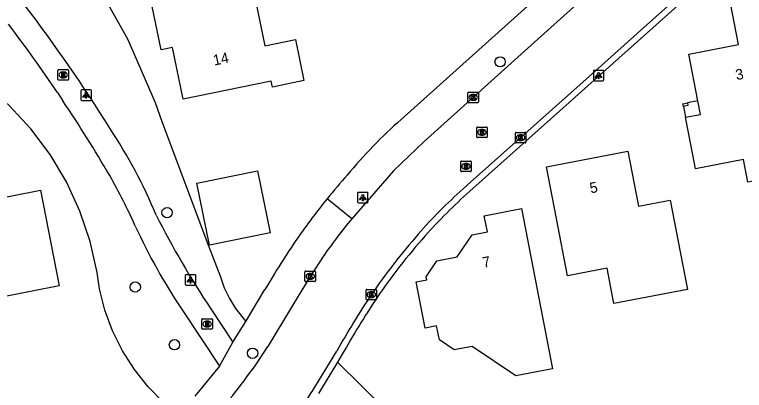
# Model space of a CAD drawing. Extents: x 157663 to 158496, y 379212 to 380934.
# Drawn here: x 158279.6 to 158348.7, y 380434.7 to 380470.3 of the extents above; entities that cross this region are included whole.
import ezdxf

# ---------------------------------------------------------------- set-up
doc = ezdxf.new("R2010")
doc.units = 0
for name, color, linetype in [('IMGEO_Boom', 7, 'Continuous'), ('IMGEO_Groenvoorziening', 7, 'Continuous'), ('IMGEO_Kolk', 7, 'Continuous'), ('IMGEO_Lichtpunt', 7, 'Continuous'), ('IMGEO_Pand', 7, 'Continuous'), ('IMGEO_Pand_nummerreeks', 7, 'Continuous'), ('IMGEO_Pand_overbouw', 7, 'Continuous'), ('IMGEO_Rijbaan_lokaal_open', 7, 'Continuous'), ('IMGEO_Rioolput', 7, 'Continuous'), ('IMGEO_Voetpad_open', 7, 'Continuous')]:
    doc.layers.add(name, color=color, linetype=linetype)

msp = doc.modelspace()

# ---------------------------------------------------------------- linework, layer by layer
at = {"layer": 'IMGEO_Boom'}
for centre in [(158325.596, 380465.83), (158294.038, 380451.528), (158291.024, 380444.477), (158294.741, 380439.004), (158302.147, 380438.192)]:
    msp.add_circle(centre, 0.489, dxfattribs=at)
at = {"layer": 'IMGEO_Groenvoorziening'}
for points in [[(158346.995, 380524.313), (158343.154, 380528.231), (158314.078, 380500), (158287.061, 380473.748), (158290.289, 380468.019), (158292.901, 380461.983), (158293.548, 380460.157), (158297.957, 380448.38), (158299.09, 380445.455), (158299.464, 380444.4), (158299.946, 380443.389), (158300.531, 380442.435), (158301.507, 380441.214)], [(158295.076, 380432.348), (158293.72, 380433.506), (158292.249, 380435.007), (158290.942, 380436.654), (158289.815, 380438.428), (158288.879, 380440.31), (158288.146, 380442.279), (158287.622, 380444.315), (158287.402, 380445.849), (158286.736, 380448.807), (158285.765, 380451.68), (158284.499, 380454.435), (158282.951, 380457.043), (158281.14, 380459.474), (158279.084, 380461.703), (158276.807, 380463.705), (158276.529, 380463.435)], [(158310.18, 380437.339), (158314.722, 380432.862), (158316.188, 380431.36), (158320.425, 380427.602), (158325.031, 380424.307), (158329.956, 380421.512), (158334.859, 380419.373)]]:
    msp.add_lwpolyline(points, dxfattribs=at)
at = {"layer": 'IMGEO_Kolk'}
for p, q in [((158322.545, 380462.026), (158322.545, 380462.878)), ((158322.62, 380462.952), (158323.472, 380462.952)), ((158323.546, 380462.878), (158323.546, 380462.026)), ((158323.056, 380462.172), (158323.031, 380462.172)), ((158323.033, 380462.732), (158323.058, 380462.732)), ((158323.472, 380461.952), (158322.62, 380461.952)), ((158327.043, 380458.213), (158327.043, 380459.065)), ((158327.118, 380459.139), (158327.97, 380459.139)), ((158327.531, 380458.919), (158327.556, 380458.919)), ((158328.044, 380459.065), (158328.044, 380458.213)), ((158327.97, 380458.139), (158327.118, 380458.139)), ((158327.554, 380458.359), (158327.529, 380458.359)), ((158307.105, 380445.063), (158307.105, 380445.915)), ((158307.18, 380445.989), (158308.032, 380445.989)), ((158307.593, 380445.769), (158307.618, 380445.769)), ((158308.106, 380445.915), (158308.106, 380445.063)), ((158308.032, 380444.989), (158307.18, 380444.989)), ((158307.616, 380445.209), (158307.591, 380445.209)), ((158312.89, 380443.33), (158312.89, 380444.182)), ((158312.965, 380444.256), (158313.817, 380444.256)), ((158313.891, 380444.182), (158313.891, 380443.33)), ((158313.401, 380443.476), (158313.376, 380443.476)), ((158313.378, 380444.036), (158313.403, 380444.036)), ((158313.817, 380443.256), (158312.965, 380443.256))]:
    msp.add_line(p, q, dxfattribs=at)
for points in [[(158322.545, 380462.026), (158322.545, 380462.878)], [(158322.62, 380462.952), (158323.472, 380462.952)], [(158323.546, 380462.878), (158323.546, 380462.026)], [(158322.866, 380462.652), (158322.989, 380462.652), (158322.989, 380462.501), (158323.119, 380462.652), (158323.283, 380462.652), (158323.137, 380462.501), (158323.29, 380462.252), (158323.138, 380462.252), (158323.053, 380462.416), (158322.989, 380462.349), (158322.989, 380462.252), (158322.866, 380462.252), (158322.866, 380462.652)], [(158323.472, 380461.952), (158322.62, 380461.952)], [(158327.043, 380458.213), (158327.043, 380459.065)], [(158327.118, 380459.139), (158327.97, 380459.139)], [(158327.364, 380458.839), (158327.487, 380458.839), (158327.487, 380458.688), (158327.617, 380458.839), (158327.781, 380458.839), (158327.635, 380458.688), (158327.788, 380458.439), (158327.636, 380458.439), (158327.551, 380458.603), (158327.487, 380458.536), (158327.487, 380458.439), (158327.364, 380458.439), (158327.364, 380458.839)], [(158328.044, 380459.065), (158328.044, 380458.213)], [(158327.97, 380458.139), (158327.118, 380458.139)], [(158307.105, 380445.063), (158307.105, 380445.915)], [(158307.18, 380445.989), (158308.032, 380445.989)], [(158307.426, 380445.689), (158307.549, 380445.689), (158307.549, 380445.538), (158307.679, 380445.689), (158307.843, 380445.689), (158307.697, 380445.538), (158307.85, 380445.289), (158307.698, 380445.289), (158307.613, 380445.453), (158307.549, 380445.386), (158307.549, 380445.289), (158307.426, 380445.289), (158307.426, 380445.689)], [(158308.106, 380445.915), (158308.106, 380445.063)], [(158308.032, 380444.989), (158307.18, 380444.989)], [(158312.89, 380443.33), (158312.89, 380444.182)], [(158312.965, 380444.256), (158313.817, 380444.256)], [(158313.891, 380444.182), (158313.891, 380443.33)], [(158313.211, 380443.956), (158313.334, 380443.956), (158313.334, 380443.805), (158313.464, 380443.956), (158313.628, 380443.956), (158313.482, 380443.805), (158313.635, 380443.556), (158313.483, 380443.556), (158313.398, 380443.72), (158313.334, 380443.653), (158313.334, 380443.556), (158313.211, 380443.556), (158313.211, 380443.956)], [(158313.817, 380443.256), (158312.965, 380443.256)]]:
    msp.add_lwpolyline(points, dxfattribs=at)
for centre, start, end in [((158322.622, 380462.876), 91.55205, 178.44795), ((158322.622, 380462.876), 91.55205, 178.44795), ((158323.47, 380462.876), 1.55205, 88.44795), ((158323.47, 380462.876), 1.55205, 88.44795), ((158322.622, 380462.028), 181.55205, 268.44795), ((158322.622, 380462.028), 181.55205, 268.44795), ((158323.47, 380462.028), 271.55205, 358.44795), ((158323.47, 380462.028), 271.55205, 358.44795), ((158327.12, 380459.063), 91.55205, 178.44795), ((158327.12, 380459.063), 91.55205, 178.44795), ((158327.968, 380459.063), 1.55205, 88.44795), ((158327.968, 380459.063), 1.55205, 88.44795), ((158327.12, 380458.215), 181.55205, 268.44795), ((158327.12, 380458.215), 181.55205, 268.44795), ((158327.968, 380458.215), 271.55205, 358.44795), ((158327.968, 380458.215), 271.55205, 358.44795), ((158307.182, 380445.913), 91.55205, 178.44795), ((158307.182, 380445.913), 91.55205, 178.44795), ((158308.03, 380445.913), 1.55205, 88.44795), ((158308.03, 380445.913), 1.55205, 88.44795), ((158307.182, 380445.065), 181.55205, 268.44795), ((158307.182, 380445.065), 181.55205, 268.44795), ((158308.03, 380445.065), 271.55205, 358.44795), ((158308.03, 380445.065), 271.55205, 358.44795), ((158312.967, 380444.18), 91.55205, 178.44795), ((158312.967, 380444.18), 91.55205, 178.44795), ((158313.815, 380444.18), 1.55205, 88.44795), ((158313.815, 380444.18), 1.55205, 88.44795), ((158312.967, 380443.332), 181.55205, 268.44795), ((158312.967, 380443.332), 181.55205, 268.44795), ((158313.815, 380443.332), 271.55205, 358.44795), ((158313.815, 380443.332), 271.55205, 358.44795)]:
    msp.add_arc(centre, 0.0765, start, end, dxfattribs=at)
for centre, major_axis, ratio, start_param, end_param in [((158323.032, 380462.452), (-0.387, 0.002), 0.722429, 4.712389, 7.853982), ((158323.057, 380462.452), (-0.39, 0.002), 0.717154, 1.570796, 4.712389), ((158327.53, 380458.639), (-0.387, 0.002), 0.722429, 4.712389, 7.853982), ((158327.555, 380458.639), (-0.39, 0.002), 0.717154, 1.570796, 4.712389), ((158307.592, 380445.489), (-0.387, 0.002), 0.722429, 4.712389, 7.853982), ((158307.617, 380445.489), (-0.39, 0.002), 0.717154, 1.570796, 4.712389), ((158313.377, 380443.756), (-0.387, 0.002), 0.722429, 4.712389, 7.853982), ((158313.402, 380443.756), (-0.39, 0.002), 0.717154, 1.570796, 4.712389)]:
    msp.add_ellipse(centre, major_axis=major_axis, ratio=ratio, start_param=start_param, end_param=end_param, dxfattribs=at)
at = {"layer": 'IMGEO_Lichtpunt'}
for p, q in [((158334.43, 380464.926), (158334.43, 380464.119)), ((158334.43, 380464.926), (158334.43, 380464.119)), ((158335.332, 380465.021), (158334.524, 380465.021)), ((158335.332, 380465.021), (158334.524, 380465.021)), ((158335.426, 380464.119), (158335.426, 380464.926)), ((158335.426, 380464.119), (158335.426, 380464.926)), ((158334.524, 380464.025), (158335.332, 380464.025)), ((158334.524, 380464.025), (158335.332, 380464.025)), ((158285.88, 380463.079), (158285.88, 380462.272)), ((158285.88, 380463.079), (158285.88, 380462.272)), ((158286.782, 380463.174), (158285.974, 380463.174)), ((158286.782, 380463.174), (158285.974, 380463.174)), ((158286.876, 380462.272), (158286.876, 380463.079)), ((158286.876, 380462.272), (158286.876, 380463.079)), ((158285.974, 380462.178), (158286.782, 380462.178)), ((158285.974, 380462.178), (158286.782, 380462.178)), ((158312.081, 380453.358), (158312.081, 380452.551)), ((158312.081, 380453.358), (158312.081, 380452.551)), ((158312.983, 380453.453), (158312.175, 380453.453)), ((158312.983, 380453.453), (158312.175, 380453.453)), ((158313.077, 380452.551), (158313.077, 380453.358)), ((158313.077, 380452.551), (158313.077, 380453.358)), ((158312.175, 380452.457), (158312.983, 380452.457)), ((158312.175, 380452.457), (158312.983, 380452.457)), ((158295.754, 380445.552), (158295.754, 380444.745)), ((158295.754, 380445.552), (158295.754, 380444.745)), ((158296.656, 380445.647), (158295.848, 380445.647)), ((158296.656, 380445.647), (158295.848, 380445.647)), ((158296.75, 380444.745), (158296.75, 380445.552)), ((158296.75, 380444.745), (158296.75, 380445.552)), ((158295.848, 380444.651), (158296.656, 380444.651)), ((158295.848, 380444.651), (158296.656, 380444.651))]:
    msp.add_line(p, q, dxfattribs=at)
for points in [[(158334.804, 380464.59), (158334.843, 380464.562), (158334.655, 380464.3), (158334.617, 380464.327), (158334.804, 380464.59)], [(158334.906, 380464.542), (158334.953, 380464.542), (158334.953, 380464.22), (158334.906, 380464.22), (158334.906, 380464.542)], [(158335.016, 380464.562), (158335.054, 380464.589), (158335.241, 380464.327), (158335.202, 380464.299), (158335.016, 380464.562)], [(158286.254, 380462.743), (158286.293, 380462.715), (158286.105, 380462.453), (158286.067, 380462.48), (158286.254, 380462.743)], [(158286.356, 380462.695), (158286.403, 380462.695), (158286.403, 380462.373), (158286.356, 380462.373), (158286.356, 380462.695)], [(158286.466, 380462.715), (158286.504, 380462.742), (158286.691, 380462.48), (158286.652, 380462.452), (158286.466, 380462.715)], [(158312.455, 380453.022), (158312.494, 380452.994), (158312.306, 380452.732), (158312.268, 380452.759), (158312.455, 380453.022)], [(158312.557, 380452.974), (158312.604, 380452.974), (158312.604, 380452.652), (158312.557, 380452.652), (158312.557, 380452.974)], [(158312.667, 380452.994), (158312.705, 380453.021), (158312.892, 380452.759), (158312.853, 380452.731), (158312.667, 380452.994)], [(158296.128, 380445.216), (158296.167, 380445.188), (158295.979, 380444.926), (158295.941, 380444.953), (158296.128, 380445.216)], [(158296.23, 380445.168), (158296.277, 380445.168), (158296.277, 380444.846), (158296.23, 380444.846), (158296.23, 380445.168)], [(158296.34, 380445.188), (158296.378, 380445.215), (158296.565, 380444.953), (158296.526, 380444.925), (158296.34, 380445.188)]]:
    msp.add_lwpolyline(points, dxfattribs=at)
for centre in [(158334.929, 380464.724), (158286.379, 380462.877), (158312.58, 380453.156), (158296.253, 380445.35)]:
    msp.add_circle(centre, 0.0994, dxfattribs=at)
for centre, start, end in [((158334.524, 380464.926), 90, 180), ((158334.524, 380464.926), 90, 180), ((158335.332, 380464.926), 0, 90), ((158335.332, 380464.926), 0, 90), ((158334.524, 380464.119), 180, 270), ((158334.524, 380464.119), 180, 270), ((158335.332, 380464.119), 270, 0), ((158335.332, 380464.119), 270, 360), ((158285.974, 380463.079), 90, 180), ((158285.974, 380463.079), 90, 180), ((158286.782, 380463.079), 0, 90), ((158286.782, 380463.079), 0, 90), ((158285.974, 380462.272), 180, 270), ((158285.974, 380462.272), 180, 270), ((158286.782, 380462.272), 270, 0), ((158286.782, 380462.272), 270, 360), ((158312.175, 380453.358), 90, 180), ((158312.175, 380453.358), 90, 180), ((158312.983, 380453.358), 0, 90), ((158312.983, 380453.358), 0, 90), ((158312.175, 380452.551), 180, 270), ((158312.175, 380452.551), 180, 270), ((158312.983, 380452.551), 270, 0), ((158312.983, 380452.551), 270, 360), ((158295.848, 380445.552), 90, 180), ((158295.848, 380445.552), 90, 180), ((158296.656, 380445.552), 0, 90), ((158296.656, 380445.552), 0, 90), ((158295.848, 380444.745), 180, 270), ((158295.848, 380444.745), 180, 270), ((158296.656, 380444.745), 270, 0), ((158296.656, 380444.745), 270, 360)]:
    msp.add_arc(centre, 0.0946, start, end, dxfattribs=at)
at = {"layer": 'IMGEO_Pand'}
for points in [[(158307.009, 380464.044), (158304.035, 380463.432), (158303.916, 380464.01), (158295.548, 380462.288), (158294.538, 380467.194), (158293.493, 380466.979), (158292.452, 380472.039), (158298.676, 380473.32), (158297.892, 380477.133), (158301.139, 380477.801), (158303.293, 380467.335), (158306.208, 380467.935), (158307.009, 380464.044)], [(158349.065, 380454.415), (158348.648, 380456.568), (158344.105, 380455.689), (158343.85, 380457.007), (158343.159, 380460.574), (158344.568, 380460.847), (158344.319, 380462.132), (158343.463, 380466.551), (158348.176, 380467.463), (158347.417, 380471.385), (158352.017, 380472.275), (158352.967, 380467.367), (158354.098, 380461.525), (158355.243, 380455.611), (158349.065, 380454.415)], [(158342.961, 380461.597), (158342.91, 380461.862), (158343.338, 380461.944), (158343.389, 380461.679), (158342.961, 380461.597)], [(158342.655, 380447.819), (158343.345, 380444.255), (158336.375, 380442.906), (158335.724, 380446.271), (158331.981, 380445.547), (158330.931, 380450.972), (158329.981, 380455.88), (158337.682, 380457.371), (158338.694, 380452.144), (158341.705, 380452.727), (158342.655, 380447.819)], [(158302.612, 380455.507), (158303.823, 380449.624), (158298.058, 380448.437), (158296.847, 380454.32), (158302.612, 380455.507)], [(158271.136, 380451.509), (158282.039, 380453.661), (158283.83, 380444.59), (158276.9, 380443.222), (158277.849, 380438.415), (158274.084, 380437.672), (158273.126, 380442.527), (158272.893, 380442.606), (158271.136, 380451.509)], [(158330.554, 380436.72), (158327.076, 380436.047), (158322.942, 380438.84), (158321.239, 380438.511), (158319.837, 380439.458), (158319.578, 380440.793), (158318.487, 380440.582), (158317.64, 380444.96), (158318.637, 380445.153), (158318.579, 380445.453), (158319.597, 380446.96), (158321.538, 380447.336), (158322.952, 380449.428), (158324.386, 380449.706), (158324.091, 380451.227), (158327.614, 380451.909), (158330.554, 380436.72)]]:
    msp.add_lwpolyline(points, dxfattribs=at)
at = {"layer": 'IMGEO_Pand_overbouw'}
msp.add_lwpolyline([(158342.961, 380461.597), (158343.159, 380460.574), (158344.568, 380460.847), (158344.319, 380462.132), (158343.338, 380461.944), (158343.389, 380461.679)], close=True, dxfattribs=at)
at = {"layer": 'IMGEO_Rijbaan_lokaal_open'}
for points in [[(158357.527, 380493.399), (158356.81, 380492.78), (158353.442, 380489.751), (158344.47, 380481.713), (158341.103, 380478.688), (158332.553, 380471.005), (158329.173, 380467.979), (158318.397, 380458.269), (158315.491, 380455.507), (158311.559, 380450.954)], [(158322.086, 380453.781), (158322.828, 380454.46), (158326.203, 380457.468), (158335.204, 380465.495), (158338.581, 380468.517), (158347.153, 380476.187), (158350.545, 380479.214), (158359.122, 380486.871)], [(158308.832, 380447.368), (158307.606, 380445.489), (158305.914, 380442.727), (158303.598, 380438.846)], [(158308.049, 380434.977), (158310.122, 380438.407)]]:
    msp.add_lwpolyline(points, dxfattribs=at)
for centre, radius, start, end in [((158354.936, 380416.967), 49.34, 131.74375, 138.75325), ((158349.161, 380419.529), 49.004, 140.11395, 145.38317), ((158367.224, 380406.641), 65.388, 139.04877, 145.41576), ((158386.696, 380395.283), 87.883, 146.52519, 150.61308), ((158260.34, 380466.486), 51.335, 319.56005, 327.42294), ((158265.429, 380462.055), 50.494, 320.73182, 327.57146)]:
    msp.add_arc(centre, radius, start, end, dxfattribs=at)
at = {"layer": 'IMGEO_Rioolput'}
for p, q in [((158283.69, 380464.168), (158283.69, 380465.02)), ((158283.765, 380465.094), (158284.617, 380465.094)), ((158284.691, 380465.02), (158284.691, 380464.168)), ((158284.201, 380464.314), (158284.176, 380464.314)), ((158284.178, 380464.874), (158284.203, 380464.874)), ((158284.617, 380464.094), (158283.765, 380464.094)), ((158323.376, 380458.718), (158323.376, 380459.57)), ((158323.451, 380459.644), (158324.303, 380459.644)), ((158323.864, 380459.424), (158323.889, 380459.424)), ((158324.377, 380459.57), (158324.377, 380458.718)), ((158323.887, 380458.864), (158323.862, 380458.864)), ((158324.303, 380458.644), (158323.451, 380458.644)), ((158321.861, 380455.491), (158321.861, 380456.343)), ((158321.936, 380456.417), (158322.788, 380456.417)), ((158322.349, 380456.197), (158322.374, 380456.197)), ((158322.862, 380456.343), (158322.862, 380455.491)), ((158322.788, 380455.417), (158321.936, 380455.417)), ((158322.372, 380455.637), (158322.347, 380455.637)), ((158297.34, 380440.548), (158297.34, 380441.4)), ((158297.415, 380441.474), (158298.267, 380441.474)), ((158298.341, 380441.4), (158298.341, 380440.548)), ((158297.828, 380441.254), (158297.853, 380441.254)), ((158298.267, 380440.474), (158297.415, 380440.474)), ((158297.851, 380440.694), (158297.826, 380440.694))]:
    msp.add_line(p, q, dxfattribs=at)
for points in [[(158283.69, 380464.168), (158283.69, 380465.02)], [(158283.765, 380465.094), (158284.617, 380465.094)], [(158284.691, 380465.02), (158284.691, 380464.168)], [(158284.279, 380464.792), (158284.027, 380464.794), (158284.027, 380464.394)], [(158284.027, 380464.394), (158284.151, 380464.394), (158284.151, 380464.556), (158284.162, 380464.556)], [(158284.205, 380464.713), (158284.151, 380464.713), (158284.151, 380464.632)], [(158284.151, 380464.632), (158284.203, 380464.632)], [(158284.209, 380464.527), (158284.28, 380464.394), (158284.42, 380464.394), (158284.355, 380464.52)], [(158284.617, 380464.094), (158283.765, 380464.094)], [(158323.376, 380458.718), (158323.376, 380459.57)], [(158323.451, 380459.644), (158324.303, 380459.644)], [(158324.377, 380459.57), (158324.377, 380458.718)], [(158323.965, 380459.342), (158323.713, 380459.344), (158323.713, 380458.944)], [(158323.713, 380458.944), (158323.837, 380458.944), (158323.837, 380459.106), (158323.848, 380459.106)], [(158323.891, 380459.263), (158323.837, 380459.263), (158323.837, 380459.182)], [(158323.837, 380459.182), (158323.889, 380459.182)], [(158323.895, 380459.077), (158323.966, 380458.944), (158324.106, 380458.944), (158324.041, 380459.07)], [(158324.303, 380458.644), (158323.451, 380458.644)], [(158321.861, 380455.491), (158321.861, 380456.343)], [(158321.936, 380456.417), (158322.788, 380456.417)], [(158322.45, 380456.115), (158322.198, 380456.117), (158322.198, 380455.717)], [(158322.376, 380456.036), (158322.322, 380456.036), (158322.322, 380455.955)], [(158322.322, 380455.955), (158322.374, 380455.955)], [(158322.862, 380456.343), (158322.862, 380455.491)], [(158322.788, 380455.417), (158321.936, 380455.417)], [(158322.198, 380455.717), (158322.322, 380455.717), (158322.322, 380455.879), (158322.333, 380455.879)], [(158322.38, 380455.85), (158322.451, 380455.717), (158322.591, 380455.717), (158322.526, 380455.843)], [(158297.34, 380440.548), (158297.34, 380441.4)], [(158297.415, 380441.474), (158298.267, 380441.474)], [(158298.341, 380441.4), (158298.341, 380440.548)], [(158297.929, 380441.172), (158297.677, 380441.174), (158297.677, 380440.774)], [(158297.677, 380440.774), (158297.801, 380440.774), (158297.801, 380440.936), (158297.812, 380440.936)], [(158297.855, 380441.093), (158297.801, 380441.093), (158297.801, 380441.012)], [(158297.801, 380441.012), (158297.853, 380441.012)], [(158297.859, 380440.907), (158297.93, 380440.774), (158298.07, 380440.774), (158298.005, 380440.9)], [(158298.267, 380440.474), (158297.415, 380440.474)]]:
    msp.add_lwpolyline(points, dxfattribs=at)
for centre, radius, start, end in [((158283.767, 380465.018), 0.0765, 91.55205, 178.44795), ((158283.767, 380465.018), 0.0765, 91.55205, 178.44795), ((158284.615, 380465.018), 0.0765, 1.55205, 88.44795), ((158284.615, 380465.018), 0.0765, 1.55205, 88.44795), ((158284.161, 380464.503), 0.0533, 26.02933, 88.69889), ((158284.187, 380464.821), 0.19, 274.7715, 282.96867), ((158284.211, 380464.617), 0.0964, 77.00612, 93.18647), ((158284.225, 380464.674), 0.0378, 276.66336, 79.67722), ((158284.278, 380464.682), 0.109, 350.36119, 89.41601), ((158284.276, 380464.682), 0.112, 277.58423, 350.98172), ((158284.26, 380464.467), 0.108, 29.51342, 73.79051), ((158283.767, 380464.17), 0.0765, 181.55205, 268.44795), ((158283.767, 380464.17), 0.0765, 181.55205, 268.44795), ((158284.615, 380464.17), 0.0765, 271.55205, 358.44795), ((158284.615, 380464.17), 0.0765, 271.55205, 358.44795), ((158323.453, 380459.568), 0.0765, 91.55205, 178.44795), ((158323.453, 380459.568), 0.0765, 91.55205, 178.44795), ((158324.301, 380459.568), 0.0765, 1.55205, 88.44795), ((158324.301, 380459.568), 0.0765, 1.55205, 88.44795), ((158323.453, 380458.72), 0.0765, 181.55205, 268.44795), ((158323.453, 380458.72), 0.0765, 181.55205, 268.44795), ((158323.847, 380459.053), 0.0533, 26.02933, 88.69889), ((158323.873, 380459.371), 0.19, 274.7715, 282.96867), ((158323.897, 380459.167), 0.0964, 77.00612, 93.18647), ((158323.911, 380459.224), 0.0378, 276.66336, 79.67722), ((158323.964, 380459.232), 0.109, 350.36119, 89.41601), ((158323.962, 380459.232), 0.112, 277.58423, 350.98172), ((158323.946, 380459.017), 0.108, 29.51342, 73.79051), ((158324.301, 380458.72), 0.0765, 271.55205, 358.44795), ((158324.301, 380458.72), 0.0765, 271.55205, 358.44795), ((158321.938, 380456.341), 0.0765, 91.55205, 178.44795), ((158321.938, 380456.341), 0.0765, 91.55205, 178.44795), ((158322.358, 380456.144), 0.19, 274.7715, 282.96867), ((158322.382, 380455.94), 0.0964, 77.00612, 93.18647), ((158322.396, 380455.997), 0.0378, 276.66336, 79.67722), ((158322.449, 380456.005), 0.109, 350.36119, 89.41601), ((158322.447, 380456.005), 0.112, 277.58423, 350.98172), ((158322.786, 380456.341), 0.0765, 1.55205, 88.44795), ((158322.786, 380456.341), 0.0765, 1.55205, 88.44795), ((158321.938, 380455.493), 0.0765, 181.55205, 268.44795), ((158321.938, 380455.493), 0.0765, 181.55205, 268.44795), ((158322.332, 380455.826), 0.0533, 26.02933, 88.69889), ((158322.431, 380455.79), 0.108, 29.51342, 73.79051), ((158322.786, 380455.493), 0.0765, 271.55205, 358.44795), ((158322.786, 380455.493), 0.0765, 271.55205, 358.44795), ((158297.417, 380441.398), 0.0765, 91.55205, 178.44795), ((158297.417, 380441.398), 0.0765, 91.55205, 178.44795), ((158298.265, 380441.398), 0.0765, 1.55205, 88.44795), ((158298.265, 380441.398), 0.0765, 1.55205, 88.44795), ((158297.811, 380440.883), 0.0533, 26.02933, 88.69889), ((158297.837, 380441.201), 0.19, 274.7715, 282.96867), ((158297.861, 380440.997), 0.0964, 77.00612, 93.18647), ((158297.875, 380441.054), 0.0378, 276.66336, 79.67722), ((158297.928, 380441.062), 0.109, 350.36119, 89.41601), ((158297.926, 380441.062), 0.112, 277.58423, 350.98172), ((158297.91, 380440.847), 0.108, 29.51342, 73.79051), ((158297.417, 380440.55), 0.0765, 181.55205, 268.44795), ((158297.417, 380440.55), 0.0765, 181.55205, 268.44795), ((158298.265, 380440.55), 0.0765, 271.55205, 358.44795), ((158298.265, 380440.55), 0.0765, 271.55205, 358.44795)]:
    msp.add_arc(centre, radius, start, end, dxfattribs=at)
for centre, major_axis, ratio, start_param, end_param in [((158284.177, 380464.594), (-0.387, 0.002), 0.722429, 4.712389, 7.853982), ((158284.202, 380464.594), (-0.39, 0.002), 0.717154, 1.570796, 4.712389), ((158323.863, 380459.144), (-0.387, 0.002), 0.722429, 4.712389, 7.853982), ((158323.888, 380459.144), (-0.39, 0.002), 0.717154, 1.570796, 4.712389), ((158322.348, 380455.917), (-0.387, 0.002), 0.722429, 4.712389, 7.853982), ((158322.373, 380455.917), (-0.39, 0.002), 0.717154, 1.570796, 4.712389), ((158297.827, 380440.974), (-0.387, 0.002), 0.722429, 4.712389, 7.853982), ((158297.852, 380440.974), (-0.39, 0.002), 0.717154, 1.570796, 4.712389)]:
    msp.add_ellipse(centre, major_axis=major_axis, ratio=ratio, start_param=start_param, end_param=end_param, dxfattribs=at)
at = {"layer": 'IMGEO_Voetpad_open'}
for points in [[(158316.229, 380460.36), (158354.917, 380495.131)], [(158359.49, 380486.443), (158322.721, 380453.552)], [(158283.644, 380462.91), (158284.17, 380462.126)], [(158311.559, 380450.954), (158309.213, 380452.852)], [(158301.507, 380441.214), (158303.311, 380444.229)], [(158295.46, 380442.322), (158298.998, 380436.979)], [(158298.178, 380442.407), (158300.265, 380439.236)], [(158300.265, 380439.236), (158301.507, 380441.214)], [(158298.998, 380436.979), (158300.265, 380439.236)], [(158310.642, 380438.099), (158310.18, 380437.339)], [(158310.18, 380437.339), (158308.372, 380434.366)], [(158298.998, 380436.979), (158296.656, 380434.134)]]:
    msp.add_lwpolyline(points, dxfattribs=at)
for centre, radius, start, end in [((158166.292, 380383.593), 143.977, 31.83545, 37.45264), ((158183.043, 380395.909), 120.87, 33.66381, 37.43998), ((158159.838, 380379.183), 149.459, 30.50385, 33.70753), ((158344.102, 380428.199), 42.559, 130.91455, 140.82657), ((158248.895, 380433.062), 47.731, 22.45847, 33.6894), ((158239.845, 380427.443), 56.037, 24.01825, 29.51255), ((158358.067, 380413.236), 62.898, 138.2947, 140.96131), ((158357.928, 380414.11), 52.87, 131.7534, 138.27355), ((158357.155, 380413.903), 61.77, 140.90888, 145.26841), ((158369.759, 380490.005), 85.962, 206.7633, 213.62205), ((158342.58, 380473.847), 56.693, 204.59446, 213.78432), ((158369.244, 380405.904), 76.263, 145.50387, 149.8315), ((158363.506, 380409.558), 60.063, 138.57377, 145.6573), ((158381.559, 380398.356), 81.294, 146.31668, 150.73314)]:
    msp.add_arc(centre, radius, start, end, dxfattribs=at)

# ---------------------------------------------------------------- texts
at = {"layer": 'IMGEO_Pand_nummerreeks'}
for s, rotation, p in [('14', 11.62823, (158298.503, 380465.468)), ('3', 10.95179, (158348.004, 380464.089)), ('5', 10.95753, (158334.185, 380453.353)), ('7', 10.97146, (158324.023, 380446.295))]:
    msp.add_text(s, height=1, rotation=rotation, dxfattribs=at).set_placement(p)

doc.saveas('drawing.dxf')
